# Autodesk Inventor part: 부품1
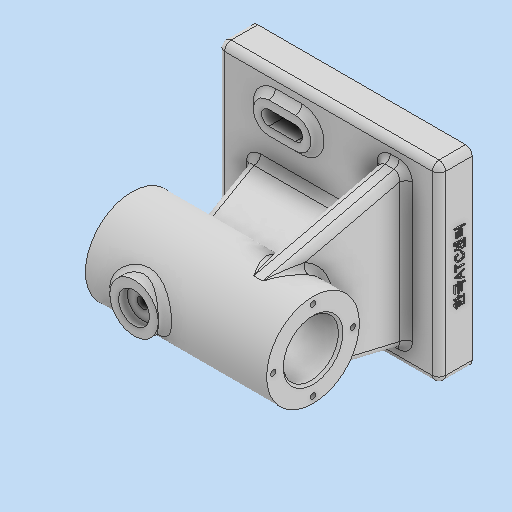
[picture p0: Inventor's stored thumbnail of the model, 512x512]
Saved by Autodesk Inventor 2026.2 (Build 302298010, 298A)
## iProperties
Created: 2026-09
Part Number: 부품1
Material: 일반
Document SubType Name: Modeling
Designer: PC2-02
Density: 1 g/cm^3
Appearance: 기본값
Mass: 234.481 g
Surface Area: 512.687 cm^2
Volume: 234.481 cm^3
Author: PC2-02
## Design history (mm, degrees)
sketch "스케치1"
  geometry: L1 (-47, -43)-(47, -43); L2 (50, -40)-(50, 40); L3 (47, 43)-(-47, 43); L4 (-50, 40)-(-50, -40); L5 (-50, -43)-(50, 43); L6 (50, -43)-(-50, 43); A1 r 3 centre (-47, 40) between (-47, 43) and (-50, 40); A2 r 3 centre (47, 40) between (50, 40) and (47, 43); A3 r 3 centre (-47, -40) between (-50, -40) and (-47, -43); A4 r 3 centre (47, -40) between (47, -43) and (50, -40); 1 further point
  constraints: 12 end point, 8 point on circle, 8 point on line, 8 tangent, 4 centre point, 3 equal radius, 2 midpoint, 2 parallel, 1 horizontal, 1 perpendicular
  dimensions: "d0" = 100 distance of L6.end L5.end; "d1" = 86 distance of L5.end L6.start; "d2" = 3 radius of A1
extrude "돌출1" new body sketch "스케치1" stored distance "d3" = 15; taper "d4" = 0 deg
sketch "스케치2"
  geometry: L1 (47, 43)-(-47, 43) reference; L2 (-47, -43)-(47, -43) reference; L3 (50.993, 27)-(-50.993, 27); L4 (-50.993, -27)-(50.993, -27); L5 (0, 60.2)-(0, -60.2) reference; L6 (-75.192, 0)-(94.199, 0) reference; L7 (-50, 40)-(-50, -40) reference; L8 (-24, 40)-(-24, -40); L9 (-24, 27)-(-12, 27); L10 (-24, 23.7)-(-12, 23.7); L11 (-12, 30.3)-(-24, 30.3); L12 (-24, -27)-(-12, -27); L13 (-24, -30.3)-(-12, -30.3); L14 (-12, -23.7)-(-24, -23.7); A1 r 3.3 centre (-24, 27) between (-24, 30.3) and (-24, 23.7); A2 r 3.3 centre (-12, 27) between (-12, 23.7) and (-12, 30.3); A3 r 3.3 centre (-24, -27) between (-24, -23.7) and (-24, -30.3); A4 r 3.3 centre (-12, -27) between (-12, -30.3) and (-12, -23.7); 3 further points
  constraints: 22 end point, 8 point on circle, 8 tangent, 6 point on line, 5 parallel, 4 centre point, 2 midpoint, 1 other
  dimensions: "d5" = 54 distance between parallel lines of L4 L3; "d6" = 26 distance between parallel lines of L7 L8; "d7" = 12 distance of L9.start L9.end; "d8" = 6.6 diameter of A2; "d9" = 6.6 diameter of A4
extrude "돌출2" cut sketch "스케치2" extent not by distance; stored distance "d10" = 0; taper "d11" = 0 deg
sketch "스케치3"
  geometry: L1 (-24, 30.3)-(-12, 30.3) reference; L2 (-12, 23.7)-(-24, 23.7) reference; L3 (-24, -23.7)-(-12, -23.7) reference; L4 (-12, -30.3)-(-24, -30.3) reference; L5 (50, -40)-(50, 40) reference; L6 (47, 43)-(-47, 43) reference; L7 (-50, 40)-(-50, -40) reference; L8 (-47, -43)-(47, -43) reference; L9 (-24, 27)-(-12, 27); L10 (-24, 20)-(-12, 20); L11 (-12, 34)-(-24, 34); L12 (-24, -27)-(-12, -27); L13 (-24, -34)-(-12, -34); L14 (-12, -20)-(-24, -20); A1 r 3.3 centre (-12, 27) between (-12, 23.7) and (-12, 30.3) reference; A2 r 3.3 centre (-24, 27) between (-24, 30.3) and (-24, 23.7) reference; A3 r 3.3 centre (-12, -27) between (-12, -30.3) and (-12, -23.7) reference; A4 r 3.3 centre (-24, -27) between (-24, -23.7) and (-24, -30.3) reference; A5 r 3 centre (47, -40) between (47, -43) and (50, -40) reference; A6 r 3 centre (47, 40) between (50, 40) and (47, 43) reference; A7 r 3 centre (-47, 40) between (-47, 43) and (-50, 40) reference; A8 r 3 centre (-47, -40) between (-50, -40) and (-47, -43) reference; A9 r 7 centre (-24, 27) between (-24, 34) and (-24, 20); A10 r 7 centre (-12, 27) between (-12, 20) and (-12, 34); A11 r 7 centre (-24, -27) between (-24, -20) and (-24, -34); A12 r 7 centre (-12, -27) between (-12, -34) and (-12, -20); 3 further points
  constraints: 16 end point, 8 point on circle, 8 tangent, 4 centre point, 4 parallel, 2 midpoint
  dimensions: "d12" = 14 diameter of A10; "d13" = 14 diameter of A12
extrude "돌출3" join sketch "스케치3" distance "d14" = 3; taper "d15" = 0 deg
sketch "스케치4"
  geometry: L1 (15, 0)-(15, 80) reference; L2 (-57, 0)-(-57, 80); L3 (-96.6, 40)-(33.6, 40) reference; C1 r 21 at (-57, 40); 1 further point
  constraints: 2 end point, 1 centre point, 1 midpoint, 1 parallel, 1 point on line
  dimensions: "d16" = 72 distance between parallel lines of L1 L2; "d17" = 42 diameter of C1
extrude "돌출4" join sketch "스케치4" distance "d18" = 82; taper "d19" = 0 deg
sketch "스케치6"
  geometry: L1 (50, -7.5)-(50, 7.5) reference; L2 (-47, 7.5)-(47, 7.5) reference; L3 (-50, -7.5)-(-50, 7.5) reference; L4 (35, 7.5)-(18.621, 52.5); L5 (-30, 7.5)-(-30, 52.5); L6 (18.621, 52.5)-(-30, 52.5); 1 further point
  constraints: 6 end point, 2 point on line, 1 horizontal, 1 parallel
  dimensions: "d29" = 70 deg angle of L2 L4; "d30" = 15 distance from line of L4.start L1; "d31" = 20 distance between parallel lines of L3 L5; "d33" = 45 vertical distance of L4.start L4.end
extrude "돌출5" join sketch "스케치6" stored distance "d34" = 10; taper "d35" = 0 deg
sketch "스케치7"
  geometry: L1 (-4.814, 20.441)-(57, 35); L2 (-4.814, -20.441)-(57, -35); L3 (72, -43)-(57, -43) reference; L4 (57, 40)-(57, -40) reference; L5 (72, 43)-(57, 43) reference; A1 r 21 centre (0, 0) between (-4.814, -20.441) and (-4.814, 20.441) reference; 1 further point
  constraints: 4 end point, 2 point on circle, 2 point on line, 2 tangent
  dimensions: "d37" = 8 distance from line of L3 L2.end; "d39" = 8 distance of L5.end L1.end
extrude "돌출6" join sketch "스케치7" stored distance "d40" = 10; taper "d41" = 0 deg
node "작업 평면1"
sketch "스케치8"
  geometry: L1 (50, -40)-(50, 40) reference; L2 (-7, -40)-(-7, 40); L3 (-32, 21)-(-32, -21) reference; L4 (-70, 0)-(70, 0) reference; C1 r 11 at (-7, 0); 1 further point
  constraints: 2 end point, 1 centre point, 1 midpoint, 1 parallel, 1 point on line
  dimensions: "d43" = 57 distance between parallel lines of L1 L2; "d44" = 22 diameter of C1
extrude "돌출7" join sketch "스케치8" stored distance "d45" = 10; taper "d46" = 0 deg
sketch "스케치9"
  geometry: C1 r 11 at (0, 0) reference; 2 further points
  constraints: 1 coincident
hole "구멍1" sketch "스케치9" at (0, 0) diameter "d47" = 4.917; stored, may be unused: countersink angle "d51" = 90 deg, drill point angle "d53" = 118 deg; dims "d48" = 12, "d49" = 14, "d50" = 4, "d52" = 17.1
sketch "스케치10"
  geometry: C1 r 21 at (0, 0) reference; C2 r 12.5 at (0, 0); 1 further point
  constraints: 1 centre point, 1 coincident
  dimensions: "d54" = 25 diameter of C2
extrude "돌출8" cut sketch "스케치10" extent not by distance; stored distance "d55" = 0; taper "d56" = 0 deg
sketch "스케치11"
  geometry: C1 r 12.5 at (0, 0) reference; C2 r 14.5 at (0, 0); 1 further point
  constraints: 1 centre point, 1 coincident
  dimensions: "d57" = 29 diameter of C2
extrude "돌출9" cut sketch "스케치11" distance "d58" = 62; taper "d59" = 0 deg
sketch "스케치12" dims "d60" = 36
  geometry: L1 (-91.2, 0)-(43.2, 0) reference; C1 r 21 at (0, 0) reference; 6 further points
  constraints: 1 coincident, 1 horizontal alignment, 1 point on line, 7 other
  dimensions: "d63" = 360 deg dimension on C1.centre point (18, 0) (derived)
hole "구멍2" sketch "스케치12" at (18, 0), (0, 18), (-18, 0), (0, -18) diameter "d65" = 2.459; stored, may be unused: countersink angle "d69" = 90 deg, drill point angle "d71" = 118 deg; dims "d66" = 8, "d67" = 14, "d68" = 4, "d70" = 10
sketch "스케치13" dims "d72" = 36
  geometry: L1 (-43.2, 0)-(91.2, 0) reference; C1 r 12.5 at (0, 0) reference; 6 further points
  constraints: 1 coincident, 1 horizontal alignment, 1 point on line, 7 other
  dimensions: "d75" = 360 deg dimension on C1.centre point (-18, 0) (derived)
hole "구멍3" sketch "스케치13" at (-18, 0), (0, -18), (18, 0), (0, 18) diameter "d77" = 2.459; stored, may be unused: countersink angle "d81" = 90 deg, drill point angle "d83" = 118 deg; dims "d78" = 8, "d79" = 4, "d80" = 2, "d82" = 10
sketch "스케치14"
  geometry: L1 (15, 80)-(15, 0) reference; L2 (-100.2, 40)-(34.2, 40) reference; 2 further points
  constraints: 1 point on line, 1 other
  dimensions: "d84" = 6 distance from line of L1 point (9, 40)
feature "엠보싱1" sketch "스케치14" dims "d85" = 0.5, "d86" = 0
fillet "모깎기1" dims "d87" = 3
chamfer "모따기1" distance "d88" = 1; stored, may be unused: second distance "d89" = 2, angle "d90" = 45 deg
fillet "모깎기2" dims "d91" = 3
node "솔리드1"
node "투영된 루프1"
node "스케치 - 원형 패턴1" dims "d63" = 360 deg (derived)
node "스케치 - 원형 패턴2" dims "d75" = 360 deg (derived)
feature "A9D066F2-1C7D-4E18-AEED-F7BC21143FA4" dims "d47" = 4.917, "d48" = 12, "d49" = 14, "d50" = 4, "d51" = 90 deg, "d52" = 17.1, "d53" = 118 deg
other parameters: "d22" = 5, "d23" = 5, "d42" = 88.5
